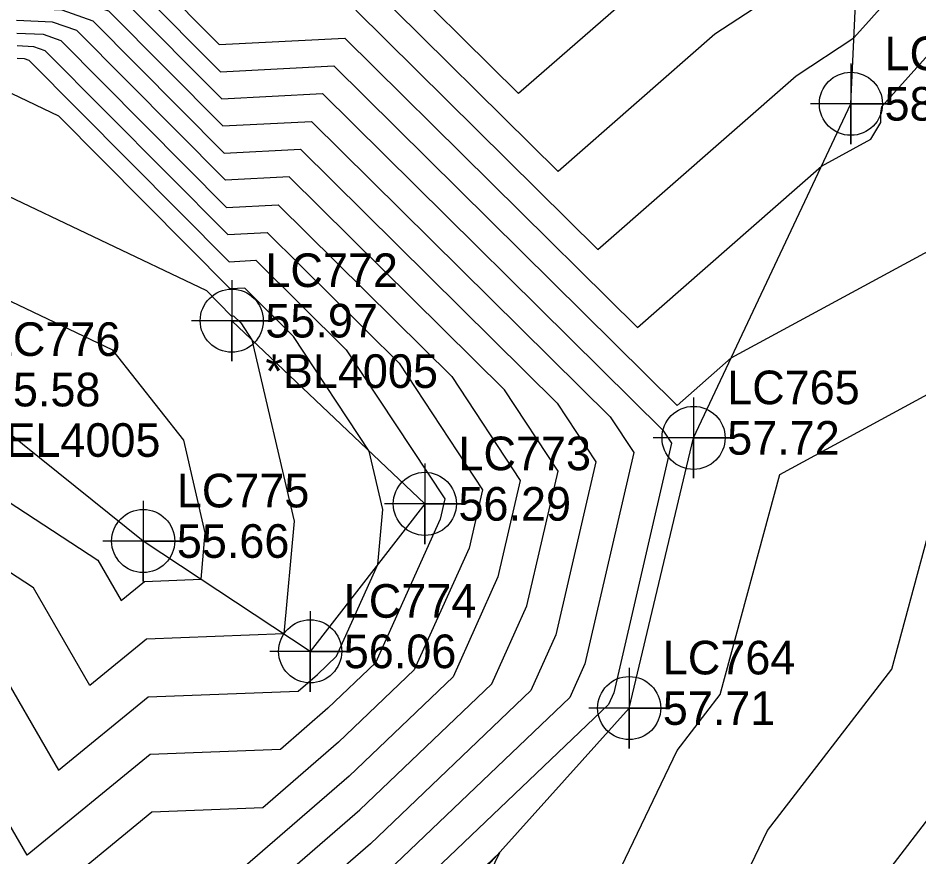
# Model space of a CAD drawing. Extents: x 2188792 to 2191981, y 386090 to 389710.
# Drawn here: x 2189631.5 to 2189698.4, y 387035.5 to 387097.8 of the extents above; entities that cross this region are included whole.
import ezdxf

# ---------------------------------------------------------------- set-up
doc = ezdxf.new("R2010")
doc.units = 0
for name, color, linetype in [('DTM Contours Major', 7, 'Continuous'), ('DTM Contours Minor', 7, 'Continuous'), ('Exist DTM Breakline', 7, 'Continuous'), ('Exist DTM Breakline Cogo Comment', 7, 'Continuous'), ('Exist DTM Breakline Cogo Elevation', 7, 'Continuous'), ('Exist DTM Breakline Cogo Number', 7, 'Continuous'), ('Exist DTM Breakline Cogo Point CELL', 7, 'Continuous')]:
    doc.layers.add(name, color=color, linetype=linetype)

msp = doc.modelspace()

# ---------------------------------------------------------------- linework, layer by layer
at = {"layer": 'DTM Contours Major'}
for points in [[(2189641.816, 387100.554), (2189646.489, 387095.847), (2189655.822, 387096.333), (2189677.572, 387074.816), (2189691.256, 387086.814), (2189694.921, 387088.803), (2189695.661, 387090.042), (2189695.67, 387090.75), (2189695.734, 387091.23), (2189711.594, 387108.94)], [(2189647.092, 387030.415), (2189656.933, 387038.945), (2189666.76, 387048.332), (2189669.357, 387054.116), (2189671.674, 387064.134), (2189667.693, 387070.172), (2189651.69, 387086.004), (2189646.945, 387085.757), (2189635.897, 387096.883), (2189634.087, 387097.52), (2189631.419, 387097.645)], [(2189608.158, 387070.883), (2189610.651, 387074.624), (2189612.783, 387079.025), (2189614.961, 387084.852), (2189619.72, 387087.595), (2189628.219, 387087.165), (2189629.715, 387085.093), (2189645.53, 387077.551), (2189647.401, 387075.666), (2189647.559, 387075.675), (2189648.091, 387075.148), (2189648.917, 387073.896), (2189652.047, 387060.417), (2189651.281, 387052.032), (2189641.071, 387051.649), (2189636.87, 387048.206), (2189632.671, 387055.451), (2189620.295, 387063.528), (2189621.25, 387064.954), (2189608.158, 387070.883)]]:
    msp.add_lwpolyline(points, dxfattribs=at)
at = {"layer": 'DTM Contours Minor'}
for points in [[(2189702.211, 387112.776), (2189694.002, 387103.617), (2189683.326, 387096.616), (2189671.683, 387086.408), (2189657.474, 387100.465), (2189646.307, 387099.883), (2189644.183, 387102.022), (2189640.25, 387103.406), (2189645.583, 387105.072), (2189647.044, 387105.263), (2189650.788, 387108.254), (2189652.763, 387109.485), (2189652.94, 387109.635), (2189659.121, 387115.832), (2189659.417, 387116.213), (2189662.235, 387123.53), (2189662.596, 387124.76), (2189662.946, 387130.891), (2189663.032, 387132.246), (2189662.032, 387138.732), (2189661.453, 387140.588), (2189658.488, 387146.37)], [(2189656.648, 387098.399), (2189674.627, 387080.612), (2189689.359, 387093.528), (2189693.664, 387096.351), (2189706.977, 387111.205)], [(2189677.292, 387099.703), (2189668.739, 387092.204), (2189658.3, 387102.531)], [(2189631.379, 387099.523), (2189635.481, 387099.33), (2189638.265, 387098.351), (2189646.763, 387089.793), (2189653.343, 387090.136), (2189675.534, 387068.182), (2189677.293, 387065.514), (2189673.661, 387049.813), (2189672.535, 387047.306), (2189658.509, 387033.907)], [(2189640.632, 387099.819), (2189646.581, 387093.829), (2189654.995, 387094.267), (2189680.516, 387069.02), (2189684.539, 387072.548), (2189699.501, 387080.666)], [(2189631.399, 387098.584), (2189634.784, 387098.425), (2189637.081, 387097.617), (2189646.854, 387087.775), (2189652.517, 387088.07), (2189671.614, 387069.177), (2189674.484, 387064.824), (2189671.509, 387051.964), (2189669.647, 387047.819), (2189657.721, 387036.426), (2189645.777, 387026.074)], [(2189639.448, 387099.085), (2189646.672, 387091.811), (2189654.169, 387092.202), (2189679.454, 387067.187), (2189680.103, 387066.204), (2189675.813, 387047.662), (2189675.423, 387046.792), (2189659.297, 387031.388)], [(2189631.439, 387096.706), (2189633.39, 387096.614), (2189634.714, 387096.149), (2189647.037, 387083.739), (2189650.864, 387083.938), (2189663.773, 387071.168), (2189668.865, 387063.443), (2189667.204, 387056.267), (2189663.872, 387048.845), (2189656.145, 387041.464), (2189648.406, 387034.756)], [(2189631.459, 387095.767), (2189632.693, 387095.709), (2189633.53, 387095.414), (2189647.128, 387081.721), (2189650.038, 387081.872), (2189659.852, 387072.163), (2189666.055, 387062.753), (2189665.052, 387058.418), (2189660.984, 387049.359), (2189655.357, 387043.982), (2189649.721, 387039.097), (2189641.487, 387038.789), (2189629.873, 387029.269)], [(2189631.479, 387094.828), (2189631.996, 387094.804), (2189632.346, 387094.68), (2189647.219, 387079.703), (2189649.212, 387079.806), (2189655.932, 387073.158), (2189663.246, 387062.063), (2189662.9, 387060.569), (2189658.097, 387049.872), (2189654.568, 387046.501), (2189651.035, 387043.439), (2189641.348, 387043.076), (2189632.206, 387035.582), (2189623.065, 387051.35)], [(2189627.868, 387053.401), (2189634.538, 387041.894), (2189641.209, 387047.363), (2189652.349, 387047.78), (2189653.78, 387049.02), (2189655.209, 387050.385), (2189658.268, 387057.198), (2189658.642, 387061.288), (2189657.635, 387065.622), (2189652.012, 387074.153), (2189648.385, 387077.74), (2189647.31, 387077.684), (2189634.559, 387090.526), (2189631.105, 387092.173)], [(2189638.578, 387073.124), (2189628.326, 387078.013), (2189627.541, 387079.1), (2189623.081, 387079.326), (2189620.584, 387077.886), (2189619.441, 387074.829), (2189618.323, 387072.52), (2189617.015, 387070.557), (2189623.884, 387067.446), (2189623.383, 387066.697), (2189637.473, 387057.502), (2189639.202, 387054.518), (2189640.932, 387055.936), (2189645.136, 387056.094), (2189645.452, 387059.546), (2189643.85, 387066.442), (2189638.578, 387073.124)], [(2189673.132, 387027.963), (2189680.522, 387043.362), (2189683.725, 387047.526), (2189688.145, 387063.883), (2189704.081, 387072.53)], [(2189682.683, 387027.922), (2189687.239, 387037.414), (2189696.471, 387049.421), (2189699.118, 387059.215)], [(2189693.956, 387031.466), (2189709.218, 387051.316)], [(2189660.086, 387028.869), (2189667.306, 387035.767), (2189663.58, 387028.004), (2189662.32, 387026.348), (2189651.251, 387021.212), (2189660.086, 387028.869)]]:
    msp.add_lwpolyline(points, dxfattribs=at)
at = {"layer": 'Exist DTM Breakline'}
for points in [[(2189607.506, 387016.831), (2189623.597, 387012.283), (2189642.272, 387014.498), (2189660.352, 387028.018), (2189676.956, 387046.52), (2189681.742, 387066.606), (2189693.435, 387091.443), (2189694.547, 387115.301), (2189671.434, 387126.078)], [(2189647.417, 387075.319), (2189661.768, 387061.7), (2189653.244, 387050.734), (2189640.835, 387058.937), (2189626.792, 387070.196)]]:
    msp.add_lwpolyline(points, dxfattribs=at)
at = {"layer": 'Exist DTM Breakline Cogo Point CELL'}
for points in [[(2189693.435, 387094.443), (2189693.435, 387088.443), (2189693.435, 387091.443), (2189696.435, 387091.443), (2189690.435, 387091.443)], [(2189647.417, 387078.319), (2189647.417, 387072.319), (2189647.417, 387075.319), (2189650.417, 387075.319), (2189644.417, 387075.319)], [(2189681.742, 387069.606), (2189681.742, 387063.606), (2189681.742, 387066.606), (2189684.742, 387066.606), (2189678.742, 387066.606)], [(2189661.768, 387064.7), (2189661.768, 387058.7), (2189661.768, 387061.7), (2189664.768, 387061.7), (2189658.768, 387061.7)], [(2189640.835, 387061.937), (2189640.835, 387055.937), (2189640.835, 387058.937), (2189643.835, 387058.937), (2189637.835, 387058.937)], [(2189653.244, 387053.734), (2189653.244, 387047.734), (2189653.244, 387050.734), (2189656.244, 387050.734), (2189650.244, 387050.734)], [(2189676.956, 387049.52), (2189676.956, 387043.52), (2189676.956, 387046.52), (2189679.956, 387046.52), (2189673.956, 387046.52)]]:
    msp.add_lwpolyline(points, dxfattribs=at)
for centre in [(2189693.435, 387091.443), (2189647.417, 387075.319), (2189681.742, 387066.606), (2189661.768, 387061.7), (2189640.835, 387058.937), (2189653.244, 387050.734), (2189676.956, 387046.52)]:
    msp.add_circle(centre, 2.344, dxfattribs=at)

# ---------------------------------------------------------------- texts
at = {"layer": 'Exist DTM Breakline Cogo Comment'}
for s, p in [('*BL4005', (2189649.917, 387070.319)), ('*EL4005', (2189629.292, 387065.196))]:
    msp.add_text(s, height=2.5, dxfattribs=at).set_placement(p)
at = {"layer": 'Exist DTM Breakline Cogo Elevation'}
for s, p in [('58.06', (2189695.935, 387090.193)), ('55.97', (2189649.917, 387074.069)), ('55.58', (2189629.292, 387068.946)), ('57.72', (2189684.242, 387065.356)), ('56.29', (2189664.268, 387060.45)), ('55.66', (2189643.335, 387057.687)), ('56.06', (2189655.744, 387049.484)), ('57.71', (2189679.456, 387045.27))]:
    msp.add_text(s, height=2.5, dxfattribs=at).set_placement(p)
at = {"layer": 'Exist DTM Breakline Cogo Number'}
for s, p in [('LC766', (2189695.935, 387093.943)), ('LC772', (2189649.917, 387077.819)), ('LC776', (2189629.292, 387072.696)), ('LC765', (2189684.242, 387069.106)), ('LC773', (2189664.268, 387064.2)), ('LC775', (2189643.335, 387061.437)), ('LC774', (2189655.744, 387053.234)), ('LC764', (2189679.456, 387049.02))]:
    msp.add_text(s, height=2.5, dxfattribs=at).set_placement(p)

doc.saveas('drawing.dxf')
